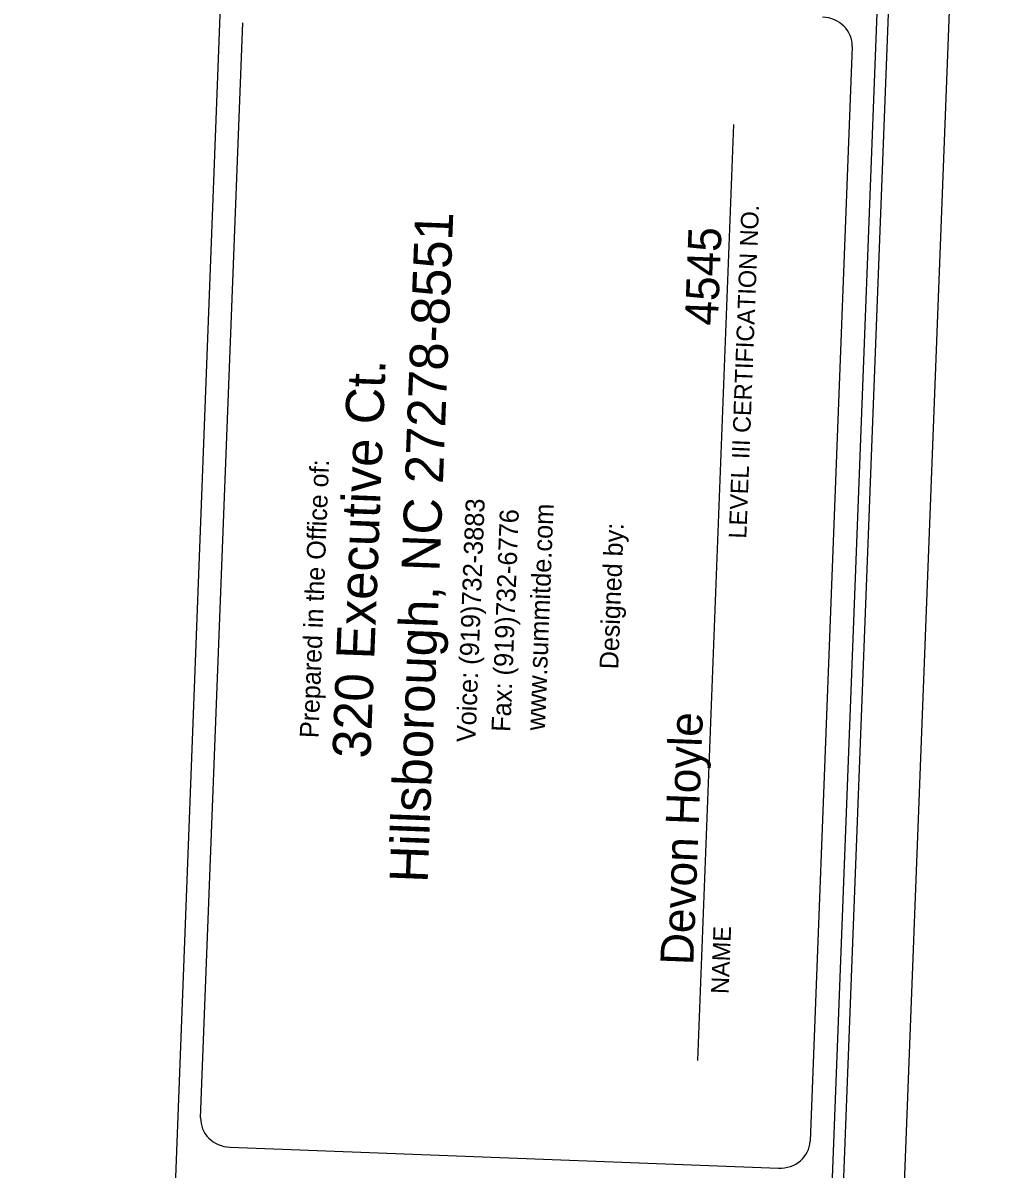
# Model space of a CAD drawing. Extents: x 1654773 to 2116434, y 680831 to 888488.
# Drawn here: x 2098950 to 2100565, y 686411 to 688306 of the extents above; entities that cross this region are included whole.
import ezdxf

# ---------------------------------------------------------------- set-up
doc = ezdxf.new("R2010")
doc.units = 0
for name, color, linetype in [('EC Title Sheet CELL', 7, 'Continuous'), ('EC Title Sheet Consultant CELL', 7, 'Continuous'), ('Sheet Plot Border Inside CELL', 7, 'Continuous'), ('Sheet Plot Border Outside CELL', 7, 'Continuous')]:
    doc.layers.add(name, color=color, linetype=linetype)

msp = doc.modelspace()

# ---------------------------------------------------------------- linework, layer by layer
at = {"layer": 'EC Title Sheet CELL'}
for p, q in [((2099079.7, 683201.5), (2099355.1, 690378.9)), ((2099243.6, 686496), (2099313.1, 688305.7)), ((2100320.5, 688266.6), (2100251.1, 686457.4)), ((2099292.3, 686447.4), (2100198.8, 686412.6))]:
    msp.add_line(p, q, dxfattribs=at)
msp.add_lwpolyline([(2100152.1, 682848.2), (2100439.3, 690334.4)], dxfattribs=at)
for centre, major_axis, start_param, end_param in [((2100270.1, 688268.6), (-50.5, 1.9), 3.141593, 4.712389), ((2099294.1, 686494.1), (-50.5, 1.9), 6.282622, 7.852769), ((2100200.6, 686459.3), (50.5, -1.9), 4.712389, 6.283185)]:
    msp.add_ellipse(centre, major_axis=major_axis, ratio=0.923408, start_param=start_param, end_param=end_param, dxfattribs=at)
at = {"layer": 'EC Title Sheet Consultant CELL'}
msp.add_line((2100065.7, 686590.8), (2100125, 688137.7), dxfattribs=at)
at = {"layer": 'Sheet Plot Border Inside CELL'}
msp.add_lwpolyline([(2095168.6, 690692.8), (2094849, 682366.6), (2100144.4, 682163.3), (2100464, 690489.5)], close=True, dxfattribs=at)
at = {"layer": 'Sheet Plot Border Outside CELL'}
msp.add_lwpolyline([(2100242.3, 682094.5), (2100565.2, 690508.2), (2095069.1, 690719.1), (2094746.1, 682305.5)], close=True, dxfattribs=at)
msp.add_lwpolyline([(2100242.3, 682094.5), (2100565.2, 690508.2), (2095069.1, 690719.1), (2094746.1, 682305.5)], close=True, dxfattribs=at)

# ---------------------------------------------------------------- texts
at = {"layer": 'EC Title Sheet CELL'}
for s, height, p in [('Hillsborough, NC 27278-8551', 62.957, (2099618.8, 686883.8)), ('LEVEL III CERTIFICATION NO.', 29.024, (2100145.6, 687453)), ('4545', 54.61, (2100098.6, 687804.9)), ('320 Executive Ct.', 62.957, (2099524.3, 687089.3)), ('Prepared in the Office of:', 30.99, (2099438.3, 687123.2)), ('Voice: (919)732-3883', 31.354, (2099697.9, 687116.2)), ('Fax: (919)732-6776', 31.354, (2099755.6, 687133.5)), ('www.summitde.com', 31.354, (2099812.8, 687135.8)), ('Designed by:', 30.99, (2099933.9, 687237)), ('Devon Hoyle', 54.613, (2100058, 686747.8)), ('NAME', 29.02, (2100116.3, 686700.4))]:
    msp.add_text(s, height=height, rotation=87.802, dxfattribs=at).set_placement(p)

doc.saveas('drawing.dxf')
